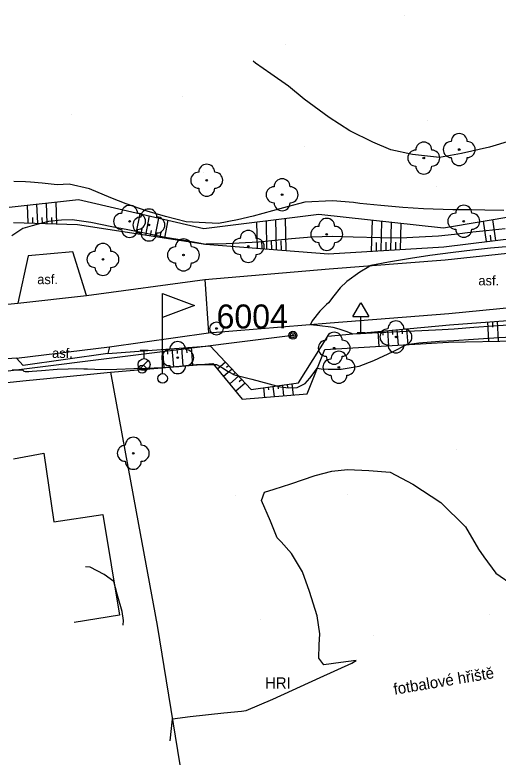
# Model space of a CAD drawing. Extents: x -448957 to -448612, y -1107690 to -1107245.
# Drawn here: x -448872.22 to -448841.97, y -1107423.46 to -1107376.57 of the extents above; entities that cross this region are included whole.
import ezdxf

# ---------------------------------------------------------------- set-up
doc = ezdxf.new("R2010")
doc.units = 0
for name, color, linetype in [('22', 7, 'Continuous'), ('25', 7, 'Continuous'), ('28', 7, 'Continuous'), ('34', 7, 'Continuous'), ('63', 7, 'Continuous'), ('Default', 7, 'Continuous'), ('Vrstva 1', 7, 'Continuous'), ('Vrstva 10', 7, 'Continuous'), ('Vrstva 14', 7, 'Continuous'), ('Vrstva 15', 7, 'Continuous'), ('Vrstva 16', 7, 'Continuous'), ('Vrstva 17', 7, 'Continuous'), ('Vrstva 22', 7, 'Continuous'), ('Vrstva 25', 7, 'Continuous'), ('Vrstva 28', 7, 'Continuous'), ('Vrstva 34', 7, 'Continuous'), ('Vrstva 40', 7, 'Continuous'), ('Vrstva 42', 7, 'Continuous'), ('Vrstva 5', 7, 'Continuous'), ('Vrstva 53', 7, 'Continuous'), ('Vrstva 63', 7, 'Continuous'), ('Vrstva 7', 7, 'Continuous'), ('Vrstva 8', 7, 'Continuous')]:
    doc.layers.add(name, color=color, linetype=linetype)

# ---------------------------------------------------------------- blocks, each defined once
blk = doc.blocks.new('POINT_DISPLAY')
at = {"layer": 'Default'}
blk.add_line((0, 0), (0, 0), dxfattribs=at)
blk = doc.blocks.new('STROM$5')
at = {"layer": '22'}
blk.add_circle((0, 0), 0.5, dxfattribs=at)
for centre, start, end in [((0, 5), 0, 180), ((-5, 0), 90, 270), ((5, 0), 270, 90), ((0, -5), 180, 0)]:
    blk.add_arc(centre, 5, start, end, dxfattribs=at)
blk = doc.blocks.new('OS_VODA')
at = {"layer": 'Default'}
for p, q in [((0, 3), (0, 53)), ((0, 53), (20, 45.5)), ((20, 45.5), (0, 38))]:
    blk.add_line(p, q, dxfattribs=at)
blk.add_circle((0, 0), 3, dxfattribs=at)
blk = doc.blocks.new('DZ$0')
at = {"layer": '34'}
for p, q in [((-5, 10), (0, 18.5)), ((0, 18.5), (5, 10)), ((-5, 10), (5, 10)), ((0, 0), (0, 10)), ((-2.49, 0), (2.49, 0))]:
    blk.add_line(p, q, dxfattribs=at)
blk = doc.blocks.new('SV$12')
at = {"layer": '28'}
blk.add_circle((0, 0), 2.5, dxfattribs=at)
blk = doc.blocks.new('HYP$10')
at = {"layer": '28'}
for p, q in [((-2.5, 9), (2.5, 9)), ((0, 3.75), (0, 9)), ((-2.65, -2.65), (2.65, 2.65))]:
    blk.add_line(p, q, dxfattribs=at)
blk.add_circle((0, 0), 3.75, dxfattribs=at)
blk = doc.blocks.new('PPBP$7')
at = {"layer": '63'}
for radius in [4.12, 0.5]:
    blk.add_circle((0, 0), radius, dxfattribs=at)
blk = doc.blocks.new('SLB$11')
at = {"layer": '25'}
for radius in [2.5, 1.58, 0.5]:
    blk.add_circle((0, 0), radius, dxfattribs=at)

msp = doc.modelspace()

# ---------------------------------------------------------------- linework, layer by layer
at = {"layer": 'Vrstva 10'}
for p, q in [((-448868.611, -1107391.37), (-448871.395, -1107391.63)), ((-448867.75, -1107394.097), (-448868.611, -1107391.37)), ((-448845.33, -1107391.868), (-448837.92, -1107391.094)), ((-448871.395, -1107391.63), (-448872.051, -1107394.581)), ((-448852.576, -1107392.441), (-448845.33, -1107391.868)), ((-448860.346, -1107393.115), (-448852.576, -1107392.441)), ((-448867.75, -1107394.097), (-448860.346, -1107393.115)), ((-448860.346, -1107393.115), (-448860.129, -1107396.437)), ((-448872.051, -1107394.581), (-448867.75, -1107394.097)), ((-448879.913, -1107395.339), (-448872.051, -1107394.581)), ((-448845.099, -1107395.225), (-448837.857, -1107394.533)), ((-448852.523, -1107395.816), (-448845.099, -1107395.225)), ((-448860.129, -1107396.437), (-448852.523, -1107395.816)), ((-448866.316, -1107397.31), (-448860.129, -1107396.437)), ((-448872.121, -1107398.014), (-448866.316, -1107397.31)), ((-448866.316, -1107397.31), (-448866.413, -1107397.724)), ((-448872.121, -1107398.014), (-448879.623, -1107398.621)), ((-448871.715, -1107398.489), (-448872.121, -1107398.014)), ((-448866.413, -1107397.724), (-448871.715, -1107398.489))]:
    msp.add_line(p, q, dxfattribs=at)
at = {"layer": 'Vrstva 14'}
for p, q in [((-448872.575, -1107388.576), (-448868.257, -1107388.103)), ((-448868.257, -1107388.103), (-448860.423, -1107389.92)), ((-448860.423, -1107389.92), (-448853.224, -1107389.021)), ((-448853.224, -1107389.021), (-448845.445, -1107389.871)), ((-448845.445, -1107389.871), (-448838.566, -1107388.715)), ((-448872.319, -1107389.541), (-448868.312, -1107389.677)), ((-448868.312, -1107389.677), (-448860.315, -1107390.891)), ((-448845.414, -1107391.056), (-448838.141, -1107390.183)), ((-448860.315, -1107390.891), (-448852.628, -1107391.495)), ((-448852.628, -1107391.495), (-448845.414, -1107391.056)), ((-448845.062, -1107395.942), (-448837.783, -1107395.389)), ((-448852.676, -1107396.643), (-448845.062, -1107395.942)), ((-448854.49, -1107399.566), (-448852.676, -1107396.643)), ((-448852.861, -1107397.481), (-448845.125, -1107397.033)), ((-448845.125, -1107397.033), (-448837.524, -1107396.869)), ((-448866.413, -1107397.724), (-448860.015, -1107397.248)), ((-448860.015, -1107397.248), (-448857.468, -1107399.984)), ((-448853.96, -1107400.264), (-448852.861, -1107397.481)), ((-448866.25, -1107398.891), (-448859.862, -1107398.353)), ((-448859.862, -1107398.353), (-448858.013, -1107400.583)), ((-448857.468, -1107399.984), (-448854.49, -1107399.566)), ((-448858.013, -1107400.583), (-448853.96, -1107400.264))]:
    msp.add_line(p, q, dxfattribs=at)
at = {"layer": 'Vrstva 15'}
for p, q in [((-448871.403, -1107389.572), (-448871.445, -1107388.452)), ((-448870.802, -1107389.592), (-448870.847, -1107388.387)), ((-448870.201, -1107389.613), (-448870.249, -1107388.321)), ((-448869.6, -1107389.633), (-448869.651, -1107388.256)), ((-448864.637, -1107390.235), (-448864.4, -1107388.998)), ((-448864.043, -1107390.325), (-448863.815, -1107389.133)), ((-448871.103, -1107389.582), (-448871.115, -1107389.238)), ((-448870.501, -1107389.603), (-448870.515, -1107389.234)), ((-448869.9, -1107389.623), (-448869.915, -1107389.23)), ((-448863.45, -1107390.415), (-448863.23, -1107389.269)), ((-448862.856, -1107390.505), (-448862.645, -1107389.405)), ((-448857.071, -1107391.146), (-448857.108, -1107389.506)), ((-448856.47, -1107391.193), (-448856.51, -1107389.431)), ((-448855.868, -1107391.24), (-448855.912, -1107389.357)), ((-448855.267, -1107391.288), (-448855.313, -1107389.282)), ((-448849.927, -1107391.331), (-448849.88, -1107389.386)), ((-448849.326, -1107391.294), (-448849.282, -1107389.452)), ((-448848.725, -1107391.257), (-448848.683, -1107389.517)), ((-448848.124, -1107391.221), (-448848.084, -1107389.583)), ((-448842.753, -1107390.737), (-448842.939, -1107389.45)), ((-448842.157, -1107390.665), (-448842.347, -1107389.35)), ((-448864.34, -1107390.28), (-448864.275, -1107389.939)), ((-448863.747, -1107390.37), (-448863.684, -1107390.043)), ((-448863.153, -1107390.46), (-448863.093, -1107390.146)), ((-448842.455, -1107390.701), (-448842.509, -1107390.325)), ((-448856.77, -1107391.17), (-448856.782, -1107390.666)), ((-448856.169, -1107391.217), (-448856.181, -1107390.679)), ((-448855.568, -1107391.264), (-448855.581, -1107390.691)), ((-448849.626, -1107391.312), (-448849.614, -1107390.786)), ((-448849.025, -1107391.276), (-448849.013, -1107390.779)), ((-448848.424, -1107391.239), (-448848.413, -1107390.771)), ((-448842.381, -1107395.738), (-448842.364, -1107396.086)), ((-448842.081, -1107395.716), (-448842.021, -1107396.966)), ((-448847.749, -1107396.189), (-448847.674, -1107397.181)), ((-448842.68, -1107395.761), (-448842.621, -1107396.979)), ((-448849.541, -1107396.354), (-448849.472, -1107397.285)), ((-448849.243, -1107396.327), (-448849.223, -1107396.593)), ((-448848.944, -1107396.299), (-448848.873, -1107397.25)), ((-448848.645, -1107396.272), (-448848.625, -1107396.543)), ((-448848.346, -1107396.244), (-448848.273, -1107397.215)), ((-448848.047, -1107396.217), (-448848.027, -1107396.494)), ((-448863.009, -1107397.471), (-448862.919, -1107398.61)), ((-448862.71, -1107397.449), (-448862.684, -1107397.774)), ((-448862.411, -1107397.426), (-448862.321, -1107398.56)), ((-448862.112, -1107397.404), (-448862.086, -1107397.728)), ((-448861.813, -1107397.382), (-448861.723, -1107398.51)), ((-448861.513, -1107397.359), (-448861.488, -1107397.682)), ((-448861.214, -1107397.337), (-448861.125, -1107398.459)), ((-448859.065, -1107398.269), (-448859.566, -1107398.71)), ((-448858.86, -1107398.489), (-448859.003, -1107398.614)), ((-448858.656, -1107398.708), (-448859.183, -1107399.172)), ((-448858.451, -1107398.928), (-448858.602, -1107399.06)), ((-448858.247, -1107399.148), (-448858.8, -1107399.634)), ((-448858.042, -1107399.367), (-448858.2, -1107399.506)), ((-448857.838, -1107399.587), (-448858.417, -1107400.096)), ((-448856.691, -1107399.875), (-448856.625, -1107400.474)), ((-448856.394, -1107399.833), (-448856.375, -1107400.004)), ((-448856.096, -1107399.791), (-448856.027, -1107400.427)), ((-448855.799, -1107399.75), (-448855.779, -1107399.931)), ((-448855.502, -1107399.708), (-448855.428, -1107400.38)), ((-448855.205, -1107399.666), (-448855.184, -1107399.858)), ((-448854.907, -1107399.625), (-448854.83, -1107400.332))]:
    msp.add_line(p, q, dxfattribs=at)
at = {"layer": 'Vrstva 16'}
for points in [[(-448841.671, -1107388.786), (-448842.85, -1107388.773), (-448843.678, -1107388.757), (-448844.855, -1107388.757), (-448846.686, -1107388.691), (-448847.973, -1107388.61), (-448849.36, -1107388.49), (-448850.657, -1107388.361), (-448851.067, -1107388.301), (-448852.381, -1107388.178), (-448854.111, -1107388.272), (-448855.217, -1107388.568), (-448856.131, -1107388.82), (-448857.329, -1107389.14), (-448858.308, -1107389.369), (-448859.507, -1107389.604), (-448861.517, -1107389.507), (-448862.823, -1107389.172), (-448863.957, -1107388.833), (-448865.265, -1107388.384), (-448866.225, -1107388.007), (-448867.572, -1107387.429), (-448868.84, -1107387.142), (-448869.585, -1107387.184), (-448870.519, -1107387.087), (-448871.258, -1107387.013), (-448871.563, -1107386.992), (-448872.295, -1107386.971)], [(-448862.527, -1107421.938), (-448862.385, -1107420.582), (-448862.368, -1107420.576), (-448861.264, -1107420.419), (-448859.17, -1107420.202), (-448858.057, -1107420.1), (-448857.777, -1107420.043), (-448856.103, -1107419.344), (-448853.137, -1107417.986), (-448851.164, -1107417.085), (-448850.899, -1107416.915), (-448851.854, -1107417.049), (-448852.915, -1107417.19), (-448853.223, -1107416.768), (-448853.209, -1107415.953), (-448853.169, -1107415.26), (-448853.334, -1107414.123), (-448853.818, -1107412.618), (-448854.247, -1107411.371), (-448854.945, -1107410.245), (-448855.582, -1107409.496), (-448855.824, -1107409.259), (-448856.254, -1107408.213), (-448856.808, -1107406.922), (-448856.634, -1107406.408), (-448856.012, -1107406.217), (-448854.983, -1107405.873), (-448853.465, -1107405.364), (-448852.408, -1107405.09), (-448851.447, -1107404.988), (-448850.104, -1107405.049), (-448848.774, -1107405.16), (-448847.353, -1107405.901), (-448845.594, -1107407.037), (-448844.061, -1107408.56), (-448843.251, -1107409.958), (-448842.908, -1107410.444), (-448842.163, -1107411.465), (-448841.015, -1107412.25)]]:
    msp.add_lwpolyline(points, dxfattribs=at)
at = {"layer": 'Vrstva 17'}
for points in [[(-448841.252, -1107384.438), (-448842.561, -1107384.824), (-448844.314, -1107385.237), (-448845.695, -1107385.469), (-448847.37, -1107385.287), (-448848.726, -1107385.001), (-448849.862, -1107384.53), (-448851.3, -1107383.803), (-448852.591, -1107382.98), (-448854.142, -1107381.838), (-448855.115, -1107381.021), (-448856.226, -1107380.257), (-448857.178, -1107379.579), (-448857.341, -1107379.453)], [(-448841.581, -1107389.942), (-448842.777, -1107390.066), (-448843.607, -1107390.15), (-448844.755, -1107390.283), (-448845.756, -1107390.388), (-448846.958, -1107390.461), (-448848.127, -1107390.526), (-448849.385, -1107390.501), (-448851.093, -1107390.452), (-448852.364, -1107390.416), (-448853.695, -1107390.463), (-448854.927, -1107390.569), (-448855.765, -1107390.637), (-448856.991, -1107390.765), (-448859.024, -1107390.876), (-448860.239, -1107390.897), (-448860.277, -1107390.902), (-448860.339, -1107390.91), (-448860.391, -1107390.904), (-448860.513, -1107390.872), (-448860.608, -1107390.847), (-448861.638, -1107390.671), (-448862.827, -1107390.472), (-448863.818, -1107390.281), (-448865.159, -1107390.006), (-448866.167, -1107389.814), (-448867.484, -1107389.537), (-448868.64, -1107389.37), (-448869.309, -1107389.387), (-448870.12, -1107389.489), (-448870.601, -1107389.599), (-448870.77, -1107389.644), (-448871.144, -1107389.754), (-448871.727, -1107389.924), (-448872.418, -1107390.376)], [(-448841.273, -1107391.036), (-448842.505, -1107391.144), (-448843.614, -1107391.265), (-448844.827, -1107391.408), (-448846.299, -1107391.608), (-448847.498, -1107391.785), (-448848.877, -1107392.031), (-448849.985, -1107392.236), (-448850.027, -1107392.26), (-448850.111, -1107392.319), (-448850.675, -1107392.654), (-448851.473, -1107393.228), (-448851.899, -1107393.629), (-448852.296, -1107394.132), (-448852.633, -1107394.568), (-448852.759, -1107394.671), (-448853.173, -1107395.087), (-448853.65, -1107395.689), (-448853.748, -1107395.916), (-448853.156, -1107395.977), (-448852.481, -1107396.057), (-448852.362, -1107396.086), (-448851.979, -1107396.186), (-448851.541, -1107396.331), (-448851.276, -1107396.443), (-448851.1, -1107396.498), (-448850.62, -1107396.475), (-448849.896, -1107396.443), (-448848.631, -1107396.385), (-448846.791, -1107396.297), (-448845.525, -1107396.233), (-448844.76, -1107396.184), (-448843.547, -1107396.094), (-448842.31, -1107395.997), (-448841.097, -1107395.909)], [(-448872.395, -1107398.757), (-448871.785, -1107398.743), (-448871.735, -1107398.782), (-448871.674, -1107398.831), (-448871.579, -1107398.866), (-448871.365, -1107398.854), (-448871.141, -1107398.84), (-448870.568, -1107398.792), (-448869.577, -1107398.722), (-448868.904, -1107398.681), (-448868.389, -1107398.673), (-448867.91, -1107398.682), (-448867.689, -1107398.69), (-448867.227, -1107398.706), (-448866.55, -1107398.724), (-448865.864, -1107398.707), (-448864.791, -1107398.672), (-448864.007, -1107398.656), (-448863.036, -1107398.599), (-448862.186, -1107398.549), (-448862.087, -1107398.542), (-448861.982, -1107398.536), (-448861.917, -1107398.528), (-448861.86, -1107398.521), (-448860.865, -1107398.41), (-448859.63, -1107398.422), (-448859.24, -1107398.63), (-448858.886, -1107398.854), (-448858.496, -1107399.059), (-448858.284, -1107399.129), (-448858.259, -1107399.134), (-448858.161, -1107399.157), (-448857.427, -1107399.341), (-448856.333, -1107399.632), (-448855.875, -1107399.76), (-448855.615, -1107399.817), (-448855.122, -1107399.877), (-448854.584, -1107399.861), (-448854.08, -1107399.612), (-448853.798, -1107399.278), (-448853.52, -1107398.915), (-448853.324, -1107398.654), (-448853.078, -1107398.682), (-448852.638, -1107398.704), (-448851.833, -1107398.713), (-448850.717, -1107398.526), (-448849.791, -1107398.175), (-448848.574, -1107397.606), (-448847.779, -1107397.187), (-448847.762, -1107397.183), (-448847.723, -1107397.178), (-448846.983, -1107397.075), (-448845.692, -1107396.953), (-448844.799, -1107396.911), (-448843.554, -1107396.83), (-448841.981, -1107396.735), (-448840.722, -1107396.66)], [(-448865.45, -1107414.706), (-448865.448, -1107414.434), (-448865.529, -1107413.867), (-448865.826, -1107412.783), (-448866.041, -1107411.991), (-448866.046, -1107411.978), (-448866.051, -1107411.977), (-448866.645, -1107411.542), (-448867.524, -1107411.092), (-448867.814, -1107411.075)]]:
    msp.add_lwpolyline(points, dxfattribs=at)
at = {"layer": 'Vrstva 5'}
for p, q in [((-448872.322, -1107404.307), (-448870.425, -1107403.968)), ((-448870.425, -1107403.968), (-448869.798, -1107408.246)), ((-448869.798, -1107408.246), (-448866.733, -1107407.796)), ((-448866.733, -1107407.796), (-448865.698, -1107414.093)), ((-448865.698, -1107414.093), (-448868.521, -1107414.557))]:
    msp.add_line(p, q, dxfattribs=at)
at = {"layer": 'Vrstva 53'}
msp.add_line((-448883.494, -1107400.177), (-448854.847, -1107396.595), dxfattribs=at)
at = {"layer": 'Vrstva 7'}
for p, q in [((-448866.25, -1107398.891), (-448864.642, -1107407.635)), ((-448879.769, -1107400.301), (-448871.513, -1107399.414)), ((-448864.642, -1107407.635), (-448863.344, -1107414.736)), ((-448863.344, -1107414.736), (-448861.913, -1107423.457))]:
    msp.add_line(p, q, dxfattribs=at)
at = {"layer": 'Vrstva 8'}
for p, q in [((-448870.237, -1107399.293), (-448866.25, -1107398.891)), ((-448871.513, -1107399.414), (-448870.237, -1107399.293))]:
    msp.add_line(p, q, dxfattribs=at)

# ---------------------------------------------------------------- block references
at = {"layer": 'Vrstva 1', "xscale": 0.1, "yscale": 0.10000000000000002}
for p in [(-448868.257, -1107388.103), (-448853.224, -1107389.021), (-448868.312, -1107389.677), (-448860.423, -1107389.92), (-448845.445, -1107389.871), (-448860.315, -1107390.891), (-448845.414, -1107391.056), (-448868.611, -1107391.37), (-448852.628, -1107391.495), (-448871.395, -1107391.63), (-448845.33, -1107391.868), (-448852.576, -1107392.441), (-448860.346, -1107393.115), (-448860.346, -1107393.115), (-448867.75, -1107394.097), (-448867.75, -1107394.097), (-448872.051, -1107394.581), (-448845.099, -1107395.225), (-448852.523, -1107395.816), (-448845.062, -1107395.942), (-448860.129, -1107396.437), (-448860.129, -1107396.437), (-448854.847, -1107396.595), (-448852.676, -1107396.643), (-448845.125, -1107397.033), (-448866.316, -1107397.31), (-448866.316, -1107397.31), (-448860.015, -1107397.248), (-448852.861, -1107397.481), (-448872.121, -1107398.014), (-448866.413, -1107397.724), (-448866.413, -1107397.724), (-448871.715, -1107398.489), (-448859.862, -1107398.353), (-448859.862, -1107398.353), (-448866.25, -1107398.891), (-448866.25, -1107398.891), (-448871.513, -1107399.414), (-448870.237, -1107399.293), (-448854.49, -1107399.566), (-448857.468, -1107399.984), (-448853.96, -1107400.264), (-448858.013, -1107400.583), (-448870.425, -1107403.968), (-448870.425, -1107403.968), (-448866.733, -1107407.796), (-448866.733, -1107407.796), (-448864.642, -1107407.635), (-448869.798, -1107408.246), (-448869.798, -1107408.246), (-448869.798, -1107408.246), (-448865.698, -1107414.093), (-448863.344, -1107414.736), (-448861.913, -1107423.457)]:
    msp.add_blockref('POINT_DISPLAY', p, dxfattribs=at)
at = {"layer": 'Vrstva 14', "xscale": 0.1, "yscale": 0.10000000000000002}
for p in [(-448847.894, -1107376.571), (-448855.342, -1107378.446), (-448861.738, -1107381.668), (-448868.7, -1107382.82), (-448846.456, -1107383.141), (-448854.103, -1107384.766), (-448860.46, -1107386.433), (-448845.85, -1107387.29), (-448844.655, -1107403.716), (-448858.407, -1107406.587), (-448851.417, -1107406.541), (-448856.854, -1107414.342), (-448842.55, -1107414.063), (-448849.79, -1107415.385), (-448855.915, -1107418.677)]:
    msp.add_blockref('POINT_DISPLAY', p, dxfattribs=at)
at = {"layer": 'Vrstva 22', "xscale": 0.1, "yscale": 0.10000000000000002}
for p in [(-448844.455, -1107384.982), (-448846.669, -1107385.513), (-448860.239, -1107386.903), (-448855.524, -1107387.808), (-448865.059, -1107389.472), (-448863.849, -1107389.699), (-448844.171, -1107389.466), (-448852.735, -1107390.284), (-448857.638, -1107391.036), (-448861.689, -1107391.571), (-448866.721, -1107391.849), (-448848.407, -1107396.695), (-448852.268, -1107397.399), (-448862.051, -1107397.991), (-448851.978, -1107398.593), (-448864.825, -1107403.972)]:
    msp.add_blockref('STROM$5', p, dxfattribs=at)
at = {"layer": 'Vrstva 25', "xscale": 0.1, "yscale": 0.10000000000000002}
for name, p in [('OS_VODA', (-448862.995, -1107399.289)), ('SLB$11', (-448854.847, -1107396.595))]:
    msp.add_blockref(name, p, dxfattribs=at)
at = {"layer": 'Vrstva 28', "xscale": 0.1, "yscale": 0.10000000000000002}
for name, p in [('HYP$10', (-448864.154, -1107398.425)), ('SV$12', (-448864.273, -1107398.713))]:
    msp.add_blockref(name, p, dxfattribs=at)
at = {"layer": 'Vrstva 34', "xscale": 0.1, "yscale": 0.10000000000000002}
msp.add_blockref('DZ$0', (-448850.594, -1107396.41), dxfattribs=at)
at = {"layer": 'Vrstva 5', "xscale": 0.1, "yscale": 0.10000000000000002}
msp.add_blockref('POINT_DISPLAY', (-448870.425, -1107403.968), dxfattribs=at)
at = {"layer": 'Vrstva 63', "xscale": 0.1, "yscale": 0.10000000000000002}
msp.add_blockref('PPBP$7', (-448859.623, -1107396.168), dxfattribs=at)

# ---------------------------------------------------------------- texts
at = {"layer": 'Vrstva 40'}
for p in [(-448870.828, -1107393.396), (-448843.254, -1107393.473), (-448869.9, -1107398.01)]:
    msp.add_text('asf.', height=0.6, dxfattribs=at).set_placement(p)
at = {"layer": 'Vrstva 42'}
msp.add_text('fotbalové hřiště', height=0.7, rotation=9.537, dxfattribs=at).set_placement((-448848.497, -1107419.07))
msp.add_text('HRI', height=0.7, dxfattribs=at).set_placement((-448856.595, -1107418.677))
at = {"layer": 'Vrstva 63'}
msp.add_text('6004', height=1.5, dxfattribs=at).set_placement((-448859.623, -1107396.168))

doc.saveas('drawing.dxf')
